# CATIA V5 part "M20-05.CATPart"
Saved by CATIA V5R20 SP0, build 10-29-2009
Part number: M20-05
Revision: ANY
Definition: UNKNOWN
Nomenclature: M20-05
Source: Unknown
Bounding box of the stored display mesh (mm): x -31.5 to 31.5, y -31.5 to 31.5, z 0 to 20
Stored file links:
  C:\Users\Utente\Desktop\IO LAVORO\3D X SITO CF\X 3D SITO CF 27-09-2020\740T\740T-20\M20-05.CATPart
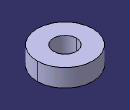
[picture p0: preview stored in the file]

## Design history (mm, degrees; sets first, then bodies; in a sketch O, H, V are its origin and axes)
Body1 "NONE" (main body)
  Solid1: solid without history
